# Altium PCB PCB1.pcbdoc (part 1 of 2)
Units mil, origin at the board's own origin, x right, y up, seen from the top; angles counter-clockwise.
Board outline 5331.95 x 5611.34 mil, 4 copper layers (Top Layer, GND, VCC, Bottom Layer); 134 components, 102 nets, 494 pads, 130 vias.
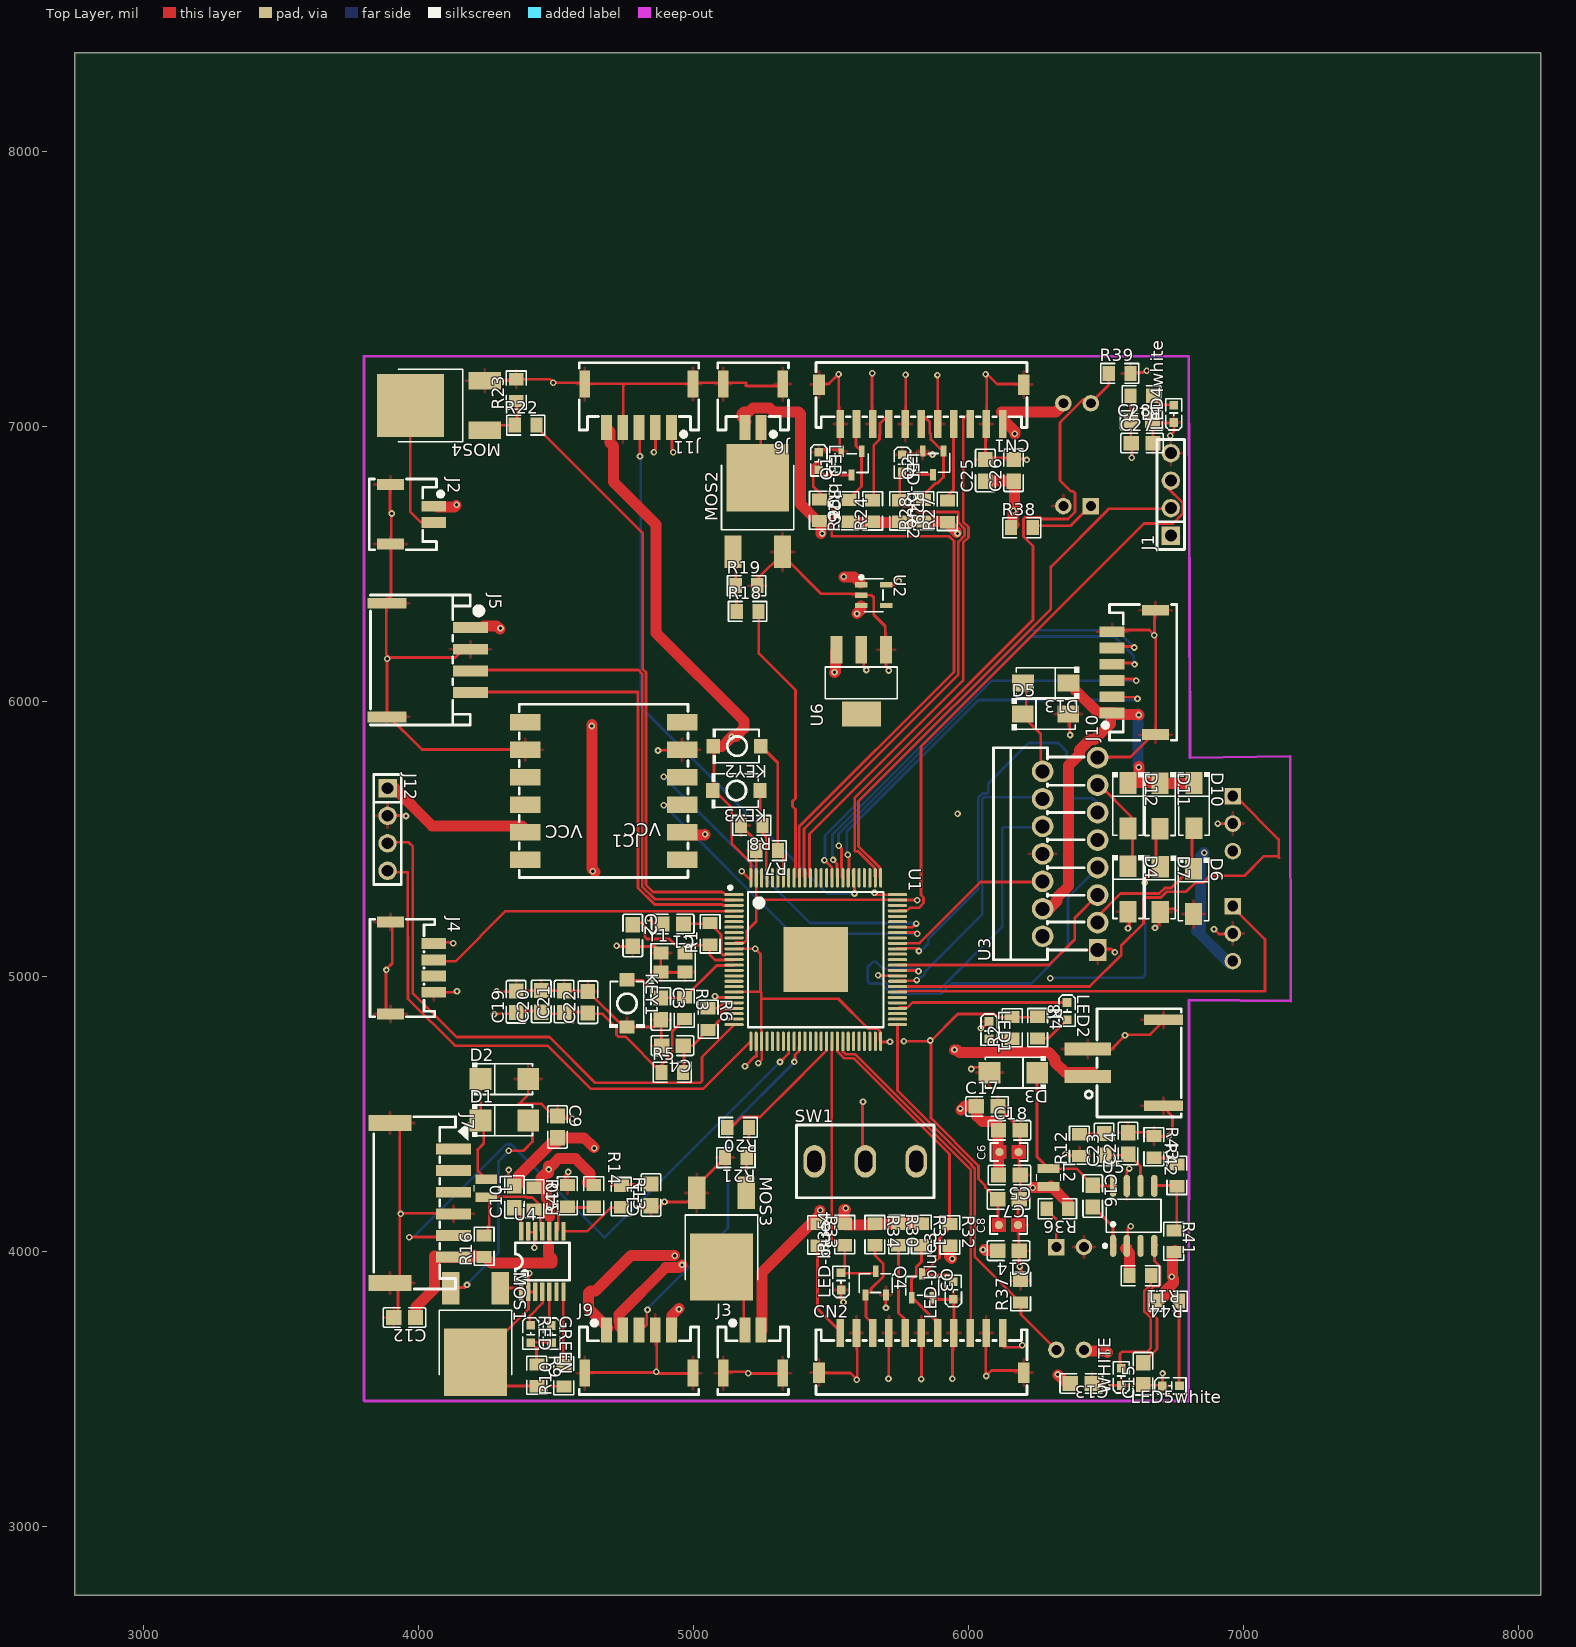
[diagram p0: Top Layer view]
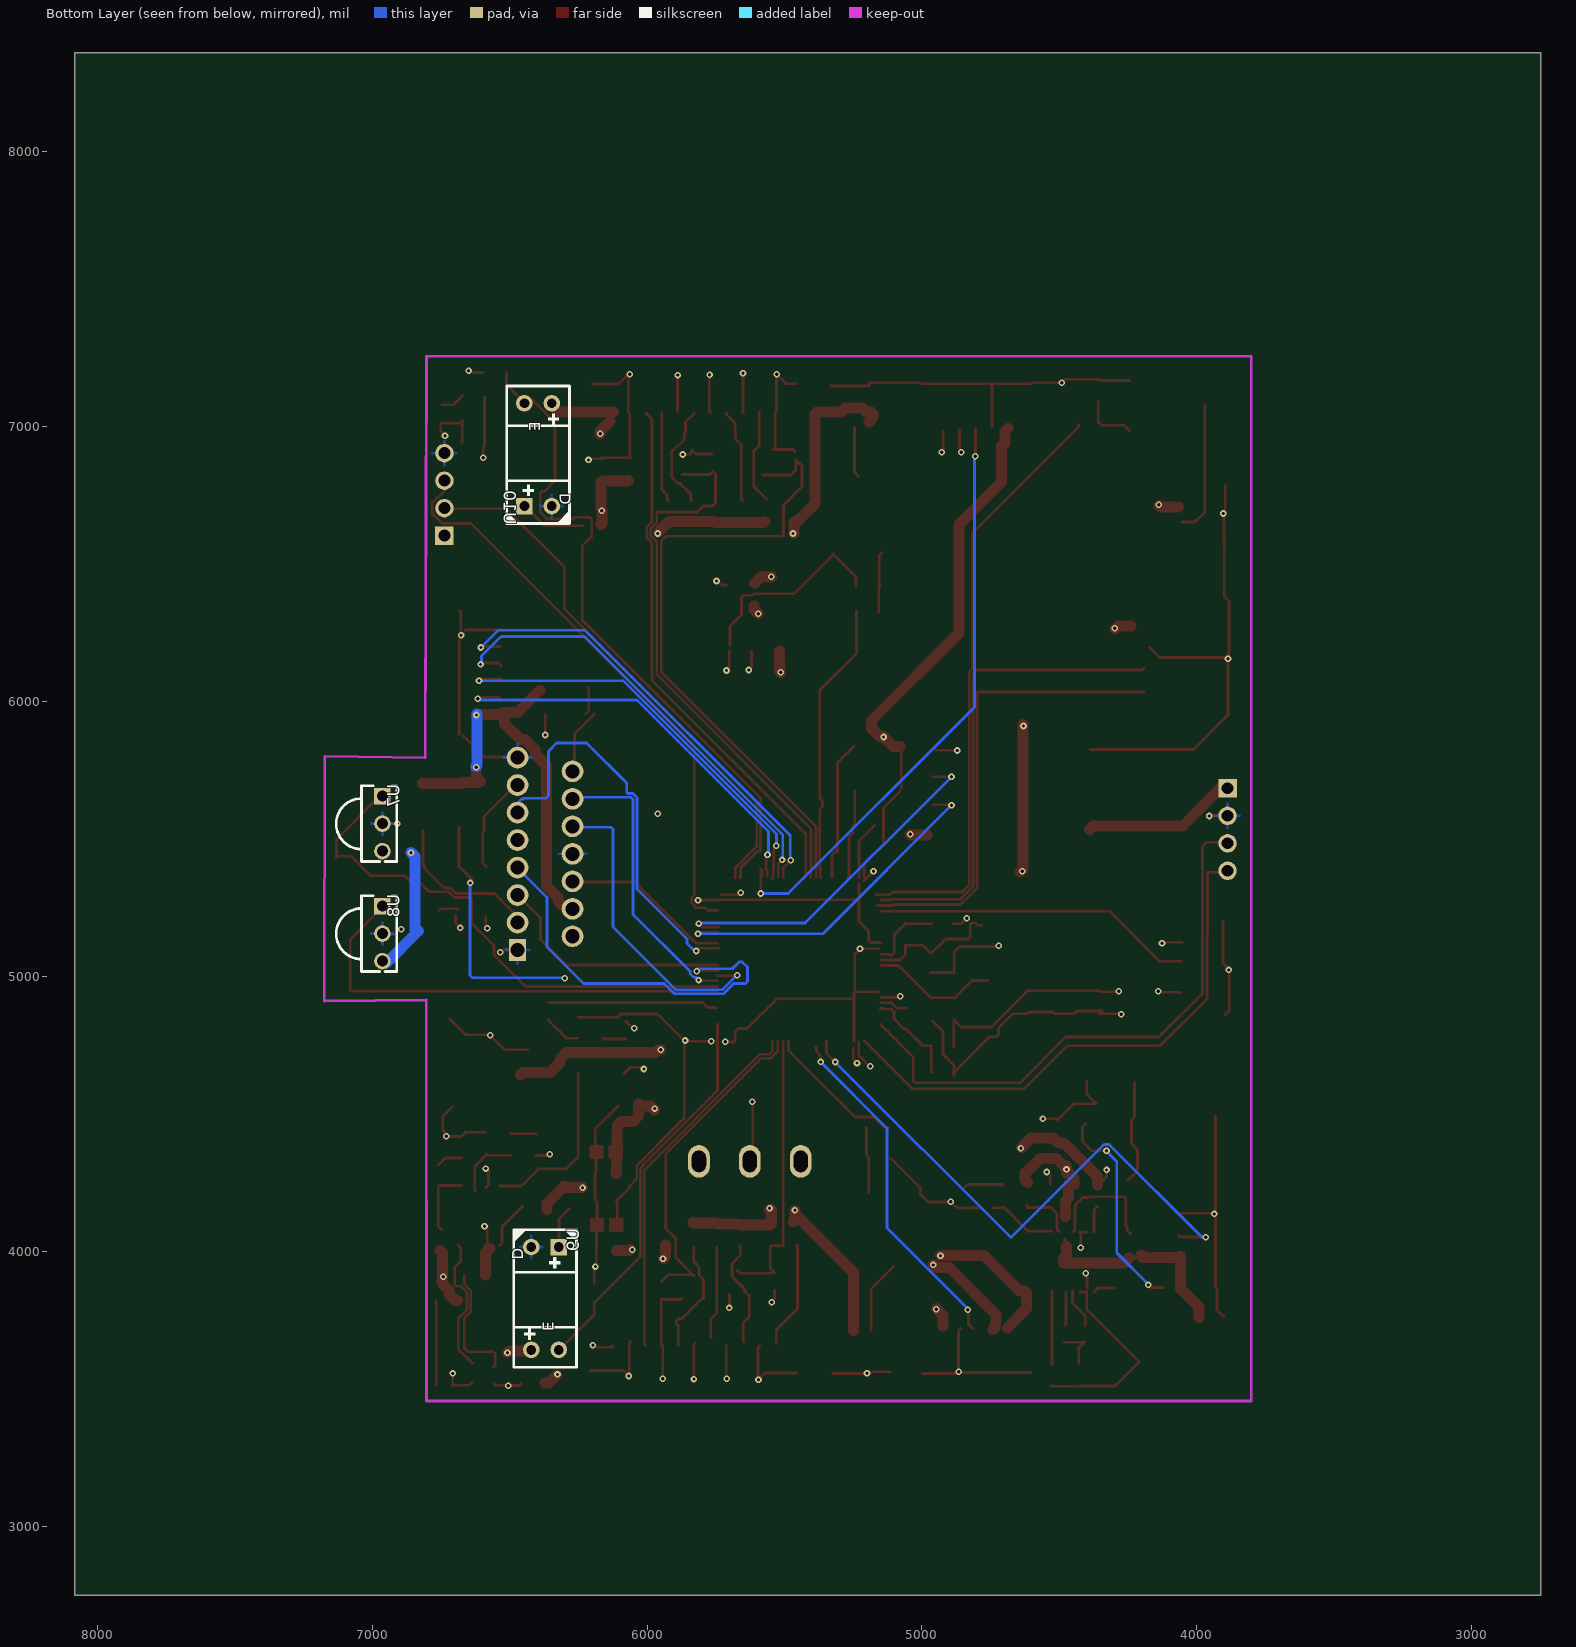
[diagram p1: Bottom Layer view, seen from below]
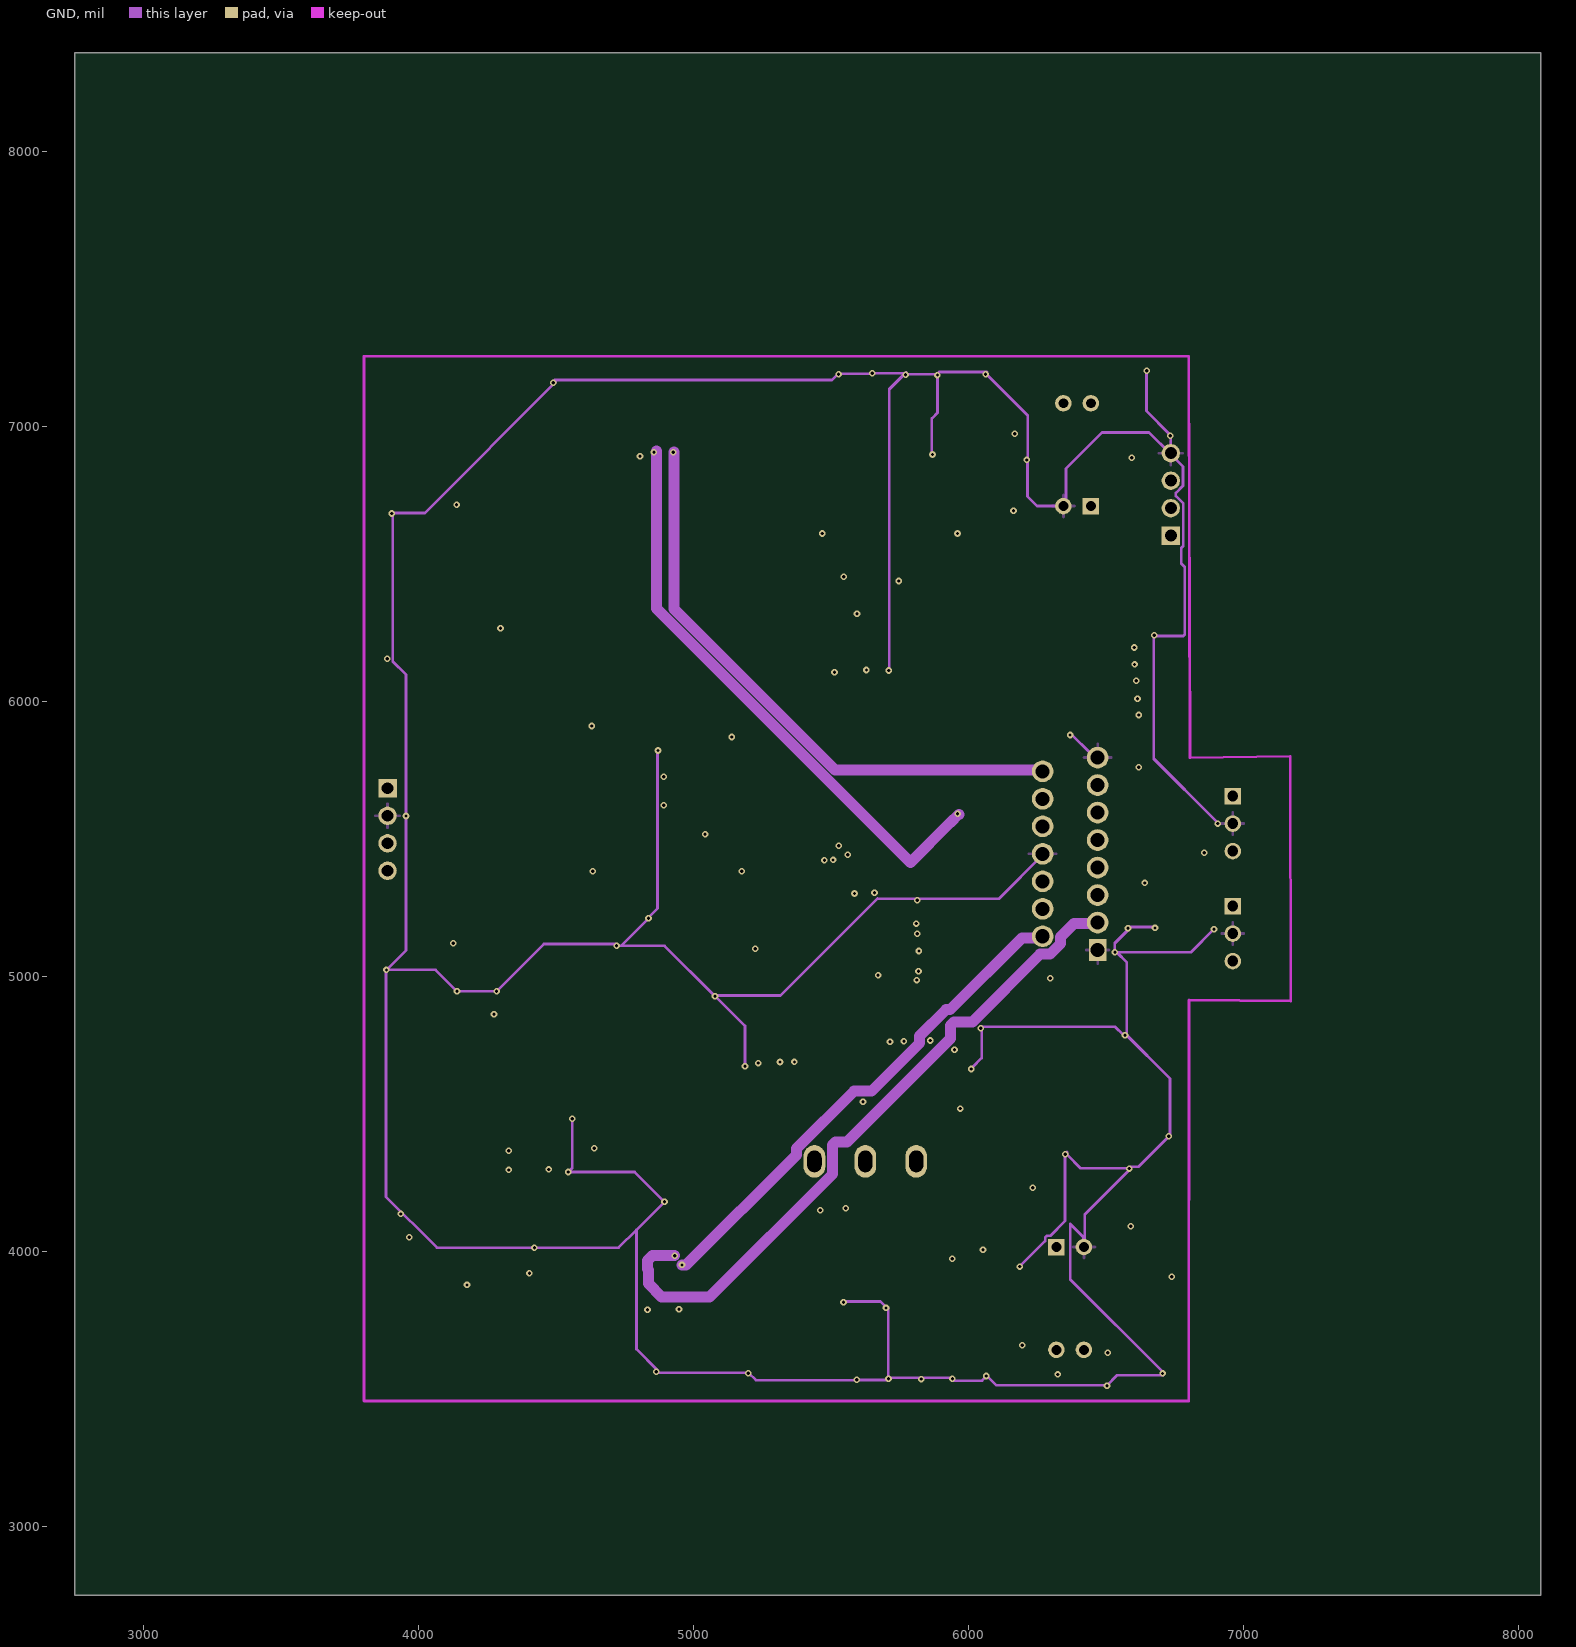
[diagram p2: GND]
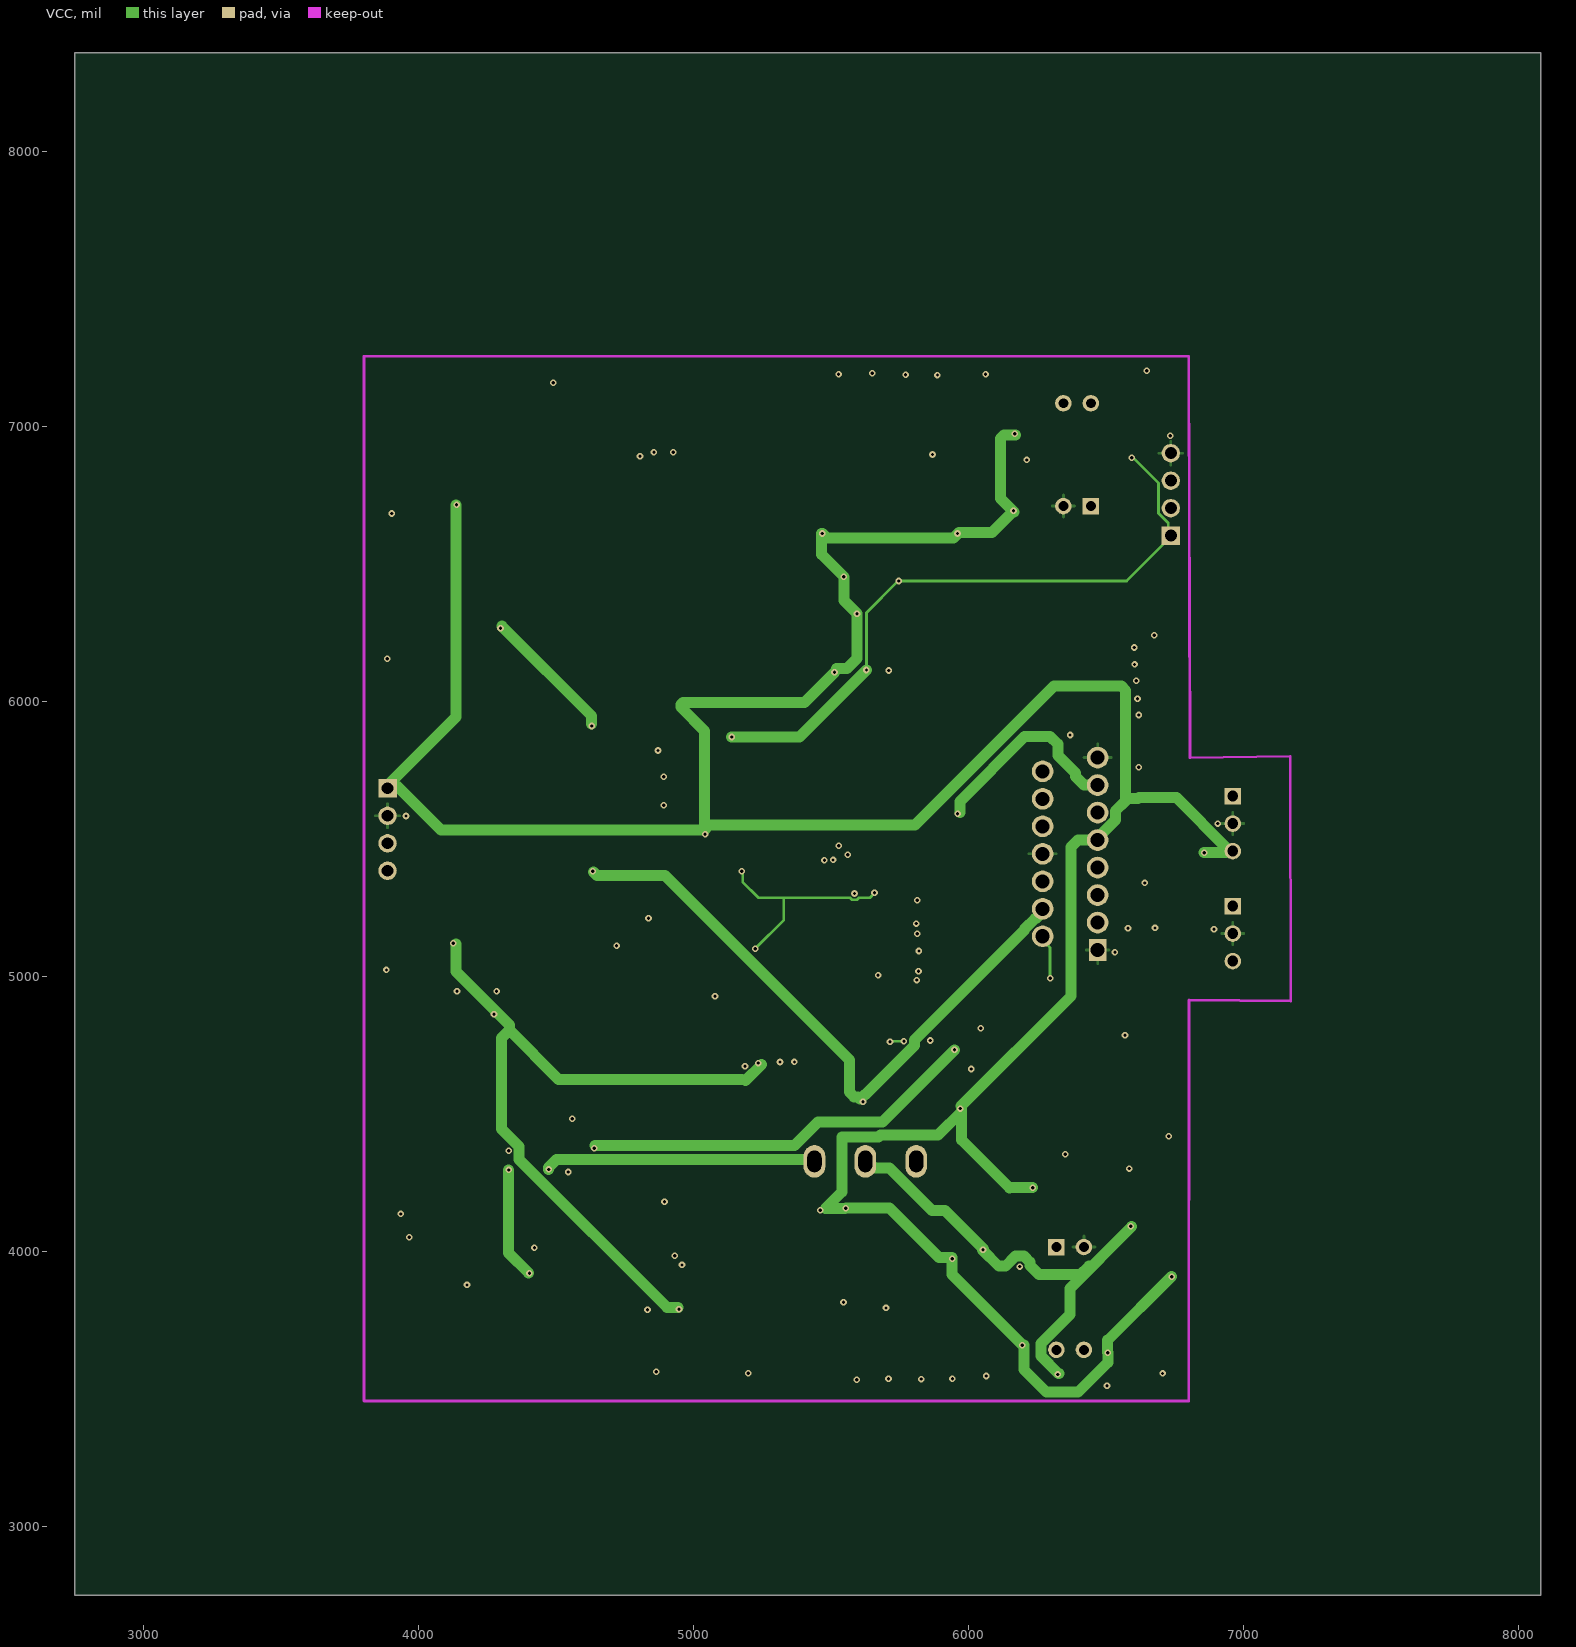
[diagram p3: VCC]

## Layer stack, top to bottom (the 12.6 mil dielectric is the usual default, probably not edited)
Top Layer: signal copper (thickness not stored)
Dielectric: dielectric 12.6, FR-4, Dk 4.8
GND: signal copper (thickness not stored)
Dielectric: dielectric 12.6, FR-4, Dk 4.8
VCC: signal copper (thickness not stored)
Dielectric: dielectric 12.6, FR-4, Dk 4.8
Bottom Layer: signal copper (thickness not stored)

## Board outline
8081.95,2750 2750,2750 2750,8361.34 8081.95,8361.34

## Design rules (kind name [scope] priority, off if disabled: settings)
BoardOutlineClearance copperThickness1oz [All] p0: genericclearance=10 ignorepadtopadclearanceinfootprint=FALSE except(0: Arc-SplitContinuation Track-SplitContinuation SMDPad-SplitContinuation THPad-SplitContinuation Via-SplitContinuation Fill-SplitContinuation Poly-SplitContinuation Region-SplitContinuation Text-SplitContinuation; 6: Track-CutoutEdge SMDPad-CutoutEdge THPad-CutoutEdge Via-CutoutEdge Region-CutoutEdge; 11.8: Track-OutlineEdge SMDPad-OutlineEdge THPad-OutlineEdge Via-OutlineEdge Fill-OutlineEdge Region-OutlineEdge Poly-OutlineEdge Text-OutlineEdge Fill-CutoutEdge)
BoardOutlineClearance copperThickness2oz [All] p0: genericclearance=10 ignorepadtopadclearanceinfootprint=FALSE except(0: Arc-SplitContinuation Track-SplitContinuation SMDPad-SplitContinuation THPad-SplitContinuation Via-SplitContinuation Fill-SplitContinuation Poly-SplitContinuation Region-SplitContinuation Text-SplitContinuation; 6: Track-CutoutEdge SMDPad-CutoutEdge THPad-CutoutEdge Via-CutoutEdge Region-CutoutEdge; 11.8: Track-OutlineEdge SMDPad-OutlineEdge THPad-OutlineEdge Via-OutlineEdge Fill-OutlineEdge Region-OutlineEdge Poly-OutlineEdge Text-OutlineEdge Fill-CutoutEdge)
Clearance copperThickness1oz [(InNet('GND') OR InNet('PH0(OSCIN)') OR InNet('PH1(OSCOUT)') OR InNet('NRST') OR InNet('VDDA') OR InNet('5V') OR InNet('3V3') OR InNet('VIN') OR InNet('$1N159') OR InNet('$1N166') OR InNet('BATTERY+') OR InNet('14V') OR InNet('$1N108') OR InNet('$1N109') OR InNet('$1N121') OR InNet('$1N220') OR InNet('$1N133') OR InNet('IR_CC_L1') OR InNet('IR_BT_FO+') OR InNet('IR_BT_FI-') OR InNet('IR_BT_LO+') OR InNet('IR_BT_LI-') OR InNet('IR_SD_O+') OR InNet('IR_SD_I-') OR InNet('IR_BT_RO+') OR InNet('IR_BT_RI-') OR InNet('IR_CC_R1') OR InNet('$1N9865') OR InNet('$1N9104') OR InNet('$1N104') OR InNet('$1N117') OR InNet('PA9(U1TX)') OR InNet('PA10(U1RX)') OR InNet('PA14(SWCLK)') OR InNet('PA13(SWDIO)') OR InNet('PUMP_O') OR InNet('RB_O') OR InNet('MAGNET') OR InNet('FAN_PWM') OR InNet('FAN_FB') OR InNet('LB_O') OR InNet('RW_O1') OR InNet('RW_O2') OR InNet('LW_O1') OR InNet('LW_O2') OR InNet('BOOT0') OR InNet('PE0') OR InNet('$1N139') OR InNet('$1N60') OR InNet('$1N82') OR InNet('PB15') OR InNet('$1N10537') OR InNet('$1N223') OR InNet('$1N8956') OR InNet('$1N9650') OR InNet('$1N125') OR InNet('$1N103') OR InNet('VREF+') OR InNet('$1N155') OR InNet('$1N156') OR InNet('$1N122') OR InNet('$1N211') OR InNet('FB') OR InNet('$1N221') OR InNet('LB_I') OR InNet('RB_I') OR InNet('PUMP_I') OR InNet('$1N110') OR InNet('PA7PWM') OR InNet('PA6PWM') OR InNet('BAT0') OR InNet('BMQ-R1') OR InNet('BMQ-L1') OR InNet('FRONT1') OR InNet('FRONT2') OR InNet('FRONT3') OR InNet('FRONT4') OR InNet('$1N26') OR InNet('$1N6') OR InNet('IR_BT_L') OR InNet('IR_BT_F') OR InNet('$1N33') OR InNet('$1N34') OR InNet('$1N35') OR InNet('TIM3CH4') OR InNet('TIM3CH3') OR InNet('RWI1') OR InNet('RWI2') OR InNet('LWI1') OR InNet('LWI2') OR InNet('IR_CC_L2') OR InNet('IR_CC_R2') OR InNet('IR_BT_R') OR InNet('IR_SD') OR InNet('$1N11') OR InNet('U2RX') OR InNet('U2TX') OR InNet('$1N18842') OR InNet('IRHIT_L') OR InNet('$1N19000') OR InNet('IRHIT_R') OR InNet('$1N27321'))] p1: gap=7 ignorepadtopadclearanceinfootprint=FALSE except(4: Track-Track; 6: Track-SMDPad SMDPad-SMDPad Track-THPad SMDPad-THPad THPad-THPad Track-Via SMDPad-Via THPad-Via Via-Via SMDPad-Fill THPad-Fill Via-Fill Fill-Fill Track-Region SMDPad-Region THPad-Region Via-Region Region-Region Track-Poly SMDPad-Poly THPad-Poly Via-Poly Fill-Poly Region-Poly Poly-Poly Track-Text SMDPad-Text THPad-Text Via-Text Fill-Text Region-Text Poly-Text Text-Text; 6.9: Track-Hole SMDPad-Hole THPad-Hole Via-Hole Fill-Hole Region-Hole Poly-Hole Text-Hole Sheet-Hole; 11.8: Track-Fill Fill-Region Track-Sheet SMDPad-Sheet THPad-Sheet Via-Sheet Fill-Sheet Region-Sheet Poly-Sheet Text-Sheet)
Clearance copperThickness2oz [All] p1: gap=7 ignorepadtopadclearanceinfootprint=FALSE except(6: Track-SMDPad SMDPad-SMDPad Track-THPad SMDPad-THPad THPad-THPad Track-Via SMDPad-Via THPad-Via Via-Via SMDPad-Fill THPad-Fill Via-Fill Fill-Fill Track-Region SMDPad-Region THPad-Region Via-Region Region-Region Track-Poly SMDPad-Poly THPad-Poly Via-Poly Fill-Poly Region-Poly Poly-Poly Track-Text SMDPad-Text THPad-Text Via-Text Fill-Text Region-Text Poly-Text Text-Text; 6.9: Track-Hole SMDPad-Hole THPad-Hole Via-Hole Fill-Hole Region-Hole Poly-Hole Text-Hole Sheet-Hole; 8: Track-Track; 11.8: Track-Fill Fill-Region Track-Sheet SMDPad-Sheet THPad-Sheet Via-Sheet Fill-Sheet Region-Sheet Poly-Sheet Text-Sheet)
DiffPairsRouting differentialPair [All] p1: maxuncoupledlength=10 minlimit=5.9843 maxlimit=5.9843 mostfreqgap=5.9843 toplayer_minwidth=5 toplayer_prefwidth=10 toplayer_maxwidth=100 bottomlayer_minwidth=5 bottomlayer_prefwidth=10 bottomlayer_maxwidth=100 midlayer1_minwidth=5 midlayer1_prefwidth=10 midlayer1_maxwidth=100 midlayer2_minwidth=5 midlayer2_prefwidth=10 midlayer2_maxwidth=100
PasteMaskExpansion pasteMaskExpansion [All] p1: expansion=0
PlaneConnect innerPlane [All] p1: planeconnectstyle=Relief reliefexpansion=20 reliefentries=4 reliefconductorwidth=10 reliefairgap=10
PolygonConnect copperRegion [All] p1: connectstyle=Relief reliefentries=4 reliefconductorwidth=10 polygonreliefangle="90 Angle" airgapwidth=10
RoutingVias viaSize [All] p1: viastyle="Through Hole" holewidth=12.0078 minholewidth=11.811 maxholewidth=248.0314 width=24.0158 minwidth=19.685 maxwidth=393.7008
SolderMaskExpansion solderMaskExpansion [All] p1: useseparateexpansions=TRUE expansion=2.0079 expansionbottom=2.0079
Width copperThickness1oz [All] p1: maxlimit=100 minlimit=5 preferedwidth=10
Width copperThickness2oz [All] p1: maxlimit=100 minlimit=8 preferedwidth=10

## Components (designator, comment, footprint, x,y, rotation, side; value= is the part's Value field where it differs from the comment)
C1 "" C0805 4925.37,5191.91 r180 top
C2 "" C0805 4780.08,5150.23 r270 top
C3 "" C0805 4881.96,4883.12 r270 top
C4 "" C0805 4924.48,4749.45 r180 top
C5 "" C0805 6149.91,4278.78 r180 top
C6 "" c8050 6108.79,4327.34 r0 top
C7 "" C0805 6146.8,4190.09 r180 top
C8 "" c8050 6106.84,4062.02 r0 top
C9 "" C0805 4506.34,4454.12 r270 top
C10 "" C0805 4349.38,4199.56 r90 top
C11 "" C0805 4846.36,4206.63 r90 top
C12 "" C0805 3950.11,3760.71 r180 top
C13 "" C0805 6411.09,3520.56 r180 top
C14 "" C0805 6146.75,4003.8 r180 top
C15 "" C0805 6636.18,3556.28 r90 top
C16 "" C0805 6453.08,4202.32 r270 top
C17 "" C0805 6069.11,4528.59 r0 top
C18 "" C0805 6149.94,4441.68 r0 top
C19 "" C0805 4355.83,4908.99 r90 top
C20 "" C0805 4447.13,4910.47 r90 top
C21 "" C0805 4530.46,4909.68 r90 top
C22 "" C0805 4616.89,4907.36 r90 top
C23 "" C0805 6494.46,4390.35 r90 top
C24 "" C0805 6581.62,4393.71 r90 top
C25 "" C0805 6062.38,6841.73 r90 top
C26 "" C0805 6165.35,6842.18 r90 top
C27 "" C0805 6632.55,6941.05 r0 top
C28 "" C0805 6631.55,7023.48 r0 top
CN1 "" CONN-SMD_11P-P1.50_HCTL_HC-ZH-11PWT 5830.05,7082.06 r180 top locked
CN2 "" CONN-SMD_11P-P1.50_HCTL_HC-ZH-11PWT 5830.04,3632.06 r0 top locked
D1 "" SMA_L4.3-W2.6-LS5.1-RD 4313.03,4477.46 r0 top
D2 "" SMA_L4.3-W2.6-LS5.1-RD 4313.09,4627.94 r0 top
D3 "" SMA_L4.3-W2.6-LS5.1-RD 6164.43,4651.41 r180 top
D4 "" SMA_L4.3-W2.5-LS5.0-RD 6581.73,5319.22 r270 top
D5 "" SMA_L4.3-W2.5-LS5.0-RD 6281.7,5955.42 r0 top
D6 "" SMA_L4.3-W2.5-LS5.0-RD 6819.97,5310.82 r270 top
D7 "" SMA_L4.3-W2.5-LS5.0-RD 6698.65,5318 r270 top
D10 "" SMA_L4.3-W2.5-LS5.0-RD 6821.27,5622.32 r270 top
D11 "" SMA_L4.3-W2.5-LS5.0-RD 6698.24,5621.08 r270 top
D12 "" SMA_L4.3-W2.5-LS5.0-RD 6581.45,5621.86 r270 top
D13 "" SMA_L4.3-W2.5-LS5.0-RD 6282.22,6068.87 r180 top
GREEN "" LED0603-RD_1 4484.27,3700.16 r270 top
IC1 "ATK-IMU901" COMM-SMD_12P-L16.0-W15.5-P2.54_ATK-IMU901 4674.14,5676 r180 top
J1 "" HDR-TH_4P-P2.54-V-M 6737.08,6754.45 r90 top
J2 "" CONN-SMD_2P-P1.50_ZX-ZH1.5-2PWT 3977.55,6682.06 r270 top locked
J3 "" CONN-SMD_2P-P1.50_ZX-ZH1.5-2PWT 5217.55,3637.06 r0 top locked
J4 "" CONN-SMD_4P-P1.50_ZX-ZH1.5-4PWT 3977.55,5032.06 r270 top locked
J5 "" CONN-SMD_4P-P2.00_USAKRO_UK-2.0-4AWT 4037.55,6152.06 r270 top locked
J6 "" CONN-SMD_2P-P1.50_ZX-ZH1.5-2PWT 5217.55,7077.06 r180 top locked
J7 "" CONN-SMD_6P-P2.00_HCTL_HC-PH-6AWT 4012.55,4177.06 r270 top locked
J8 "" CONN-SMD_2P-P2.54_USAKRO_UK-2.54-2AWT 6572.55,4687.06 r90 top locked
J9 "" CONN-SMD_5P-P1.50_ZX-ZH1.5-5PWT 4802.55,3637.06 r0 top locked
J10 "" CONN-SMD_6P-P1.50_ZX-ZH1.5-6PWT 6602.55,6107.06 r90 top locked
J11 "" CONN-SMD_5P-P1.50_ZX-ZH1.5-5PWT 4802.55,7077.06 r180 top locked
J12 "" HDR-TH_4P-P2.54-V-M 3888.29,5535.56 r270 top
KEY1 "" SW-SMD_L3.9-W3.0-P4.45 4759.12,4903.24 r270 top
KEY2 "" SW-SMD_L3.9-W3.0-P4.45 5159.34,5838.9 r180 top
KEY3 "" SW-SMD_L3.9-W3.0-P4.45 5156.87,5677.31 r180 top
L1 "" IND-SMD_L2.5-W2.0-VLS252012CX-150M 4246.63,4230.87 r270 top
L2 "" IND-SMD_L2.5-W2.0-VLS252012CX-150M 6292.17,4269.58 r270 top
LED1 "" LED0603-RD_1 6075.86,4805.99 r270 top
LED2 "" LED0603-RD_1 6359.72,4874.9 r270 top
LED4white "" LED0603-RD_1 6748.06,7047.36 r90 top
LED5white "" LED0603-RD_1 6737.44,3511.85 r0 top
LED-blue "" LED0603-RD_1 5456.76,6876.09 r270 top
LED-blue2 "" LED0603-RD_1 5760.45,6867.66 r270 top
LED-blue3 "" LED0603-RD_1 5946.23,3859.01 r90 top
LED-blue4 "" LED0603-RD_1 5537.74,3892.07 r90 top
MOS1 "" TO-252-2_L6.6-W6.1-P4.57-LS10.1-TL-CW 4207.84,3732.51 r270 top
MOS2 "" TO-252-2_L6.6-W6.1-P4.57-LS10.1-TL-CW 5234.47,6680.18 r90 top
MOS3 "" TO-252-2_L6.6-W6.1-P4.57-LS10.1-TL-CW 5102.46,4079.15 r270 top
MOS4 "" TO-252-2_L6.6-W6.1-P4.57-LS10.1-TL-CW 4107.05,7077.62 r180 top
Q1 "" SOT-23-3_L3.0-W1.7-P0.95-LS2.9-BR 5575.95,6868 r90 top
Q2 "" SOT-23-3_L3.0-W1.7-P0.95-LS2.9-BR 5872.47,6869.41 r90 top
Q3 "" SOT-23-3_L3.0-W1.7-P0.95-LS2.9-BR 5832.49,3876.03 r270 top
Q4 "" SOT-23-3_L3.0-W1.7-P0.95-LS2.9-BR 5663.57,3885.66 r270 top
R1 "" R0805 5061.35,5155.85 r90 top
R2 "" R0805 6160.18,4814.36 r90 top
R3 "" R0805 4967.64,4885.88 r270 top
R4 "" R0805 6252.59,4815.17 r270 top
R5 "" R0805 4923.57,4652.42 r0 top
R6 "" R0805 5054.09,4845.79 r270 top
R7 "" R0805 5268.92,5458.93 r180 top
R8 "" R0805 5212.93,5550.32 r180 top
R9 "" R0805 4431.11,3550.31 r270 top
R10 "" R0805 4529.36,3548.96 r90 top
R11 "" R0805 6626.45,3912.74 r180 top
R12 "" R0805 6404.64,4387.37 r90 top
R13 "" R0805 4738.38,4200.69 r270 top
R14 "" R0805 4638.04,4203.24 r270 top
R15 "" R0805 4420.55,4192.9 r270 top
R16 "" R0805 4239.47,4019.98 r90 top
R17 "" R0805 6630.06,7113.4 r180 top
R18 "" R0805 5197.68,6328.78 r0 top
R19 "" R0805 5193.94,6422.5 r0 top
R20 "" R0805 5163.12,4451.86 r180 top
R21 "" R0805 5155.08,4342.28 r180 top
R22 "" R0805 4390.64,7006.82 r0 top
R23 "" R0805 4356.38,7133.87 r90 top
R24 "510R" R0805 5652.24,6694.32 r90 top
R25 "10k" R0805 5566.01,6694.8 r90 top
R26 "1k" R0805 5459.08,6696.82 r270 top
R27 "510R" R0805 5924.21,6692.76 r90 top
R28 "10k" R0805 5838.13,6695.13 r90 top
R29 "1k" R0805 5750.45,6694.31 r270 top
R30 "510R" R0805 5746.97,4062.41 r270 top
R31 "10k" R0805 5830.22,4062.74 r270 top
R32 "1k" R0805 5933.71,4060.95 r270 top
R33 "510R" R0805 5453.22,4061.05 r270 top
R34 "10k" R0805 5660.76,4062.42 r270 top
R35 "1k" R0805 5550.96,4062.37 r90 top
R36 "200R" R0805 6324.86,4156.09 r180 top
R37 "1k" R0805 6190.72,3854.94 r90 top
R38 "200R" R0805 6195.15,6633.45 r0 top
R39 "1k" R0805 6551,7194.5 r0 top
R40 "" R0805 4542.3,4203.22 r90 top
R41 "" R0805 6748.15,4037.84 r270 top
R42 "" R0805 6759.15,4277.61 r270 top
R43 "" R0805 6675.61,4381.38 r270 top
R44 "1k" R0805 6727.44,3820.32 r180 top
RED "" LED0603-RD_1 4408.7,3700.51 r270 top
SW1 "" SW-TH_SS-12D10L5 5626.04,4328.52 r0 top
U1 "" LQFP-100_L14.0-W14.0-P0.50-LS16.0-BL-EP6.0 5445.71,5062.41 r270 top
U2 "" SOT-23-5_L3.0-W1.7-P0.95-LS2.8-BL 5656.47,6388.03 r270 top
U3 "" MULTIWATT-15_L19.6-W5.0-P1.27-L 6370.99,5447.28 r90 top
U4 "" TSSOP-14_L5.0-W4.4-P0.65-LS6.4-BL 4451.2,3964.32 r0 top
U5 "" SOIC-8_L4.9-W3.9-P1.27-LS6.0-BL 6602.1,4130.26 r0 top
U6 "" SOT-223-3_L6.5-W3.4-P2.30-LS7.0-BR 5611.27,6072.61 r90 top
U7 "" OPTO-TH_3P-L7.0-W5.6-P2.54-L 6962.55,5557.06 r270 bottom locked
U8 "" OPTO-TH_3P-L7.0-W5.6-P2.54-L 6962.55,5157.06 r270 bottom locked
U9 "" OPTO-TH_L12.7-W5.8_ST150 6371.01,3830.06 r270 bottom
U10 "" OPTO-TH_L12.7-W5.8_ST150 6396.37,6899.05 r90 bottom locked
WHITE "" LED0603-RD_1 6556.93,3544.64 r90 top
Y1 "" OSC-SMD_4P-L3.2-W2.5-BL 4926.28,5051.7 r0 top

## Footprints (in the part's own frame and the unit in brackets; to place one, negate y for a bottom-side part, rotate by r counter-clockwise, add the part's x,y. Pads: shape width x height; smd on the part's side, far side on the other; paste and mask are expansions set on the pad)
C0805 [mm]
  rect 1.41x1.35 smd: 1(-1,0) 2(1,0)
  silkscreen extent -1.96,-0.9 1.96,0.9
c8050 [mil]
  oval 30x30.13 smd: 1(5,34.97)
  oval 30.35x30 smd: 2(74.71,35)
  Top Layer region: -20,9.95 29.95,9.95 30,9.9 30,60.12 29.88,60 -20,60
  Top Layer region: 49.41,59.95 50,59.36 50,10 100,10 100,60 49.46,60
  silkscreen extent -28,2 108,68
COMM-SMD_12P-L16.0-W15.5-P2.54_ATK-IMU901 [mm]
  rect 2.8x1.524 smd: 1(-7.25,6.35) 2(-7.25,3.81) 3(-7.25,1.27) 4(-7.25,-1.27) 5(-7.25,-3.81) 6(-7.25,-6.35) 7(7.25,-6.35) 8(7.25,-3.81) 9(7.25,-1.27) 10(7.25,1.27) 11(7.25,3.81) 12(7.25,6.35)
  silkscreen extent -7.8,-8 7.8,8
CONN-SMD_2P-P1.50_ZX-ZH1.5-2PWT [mm]
  rect 1x2.3 smd: 1(-0.75,2) 2(0.75,2)
  rect 1x2.5 smd: 3(2.75,-2) 4(-2.75,-2)
  silkscreen extent -3.27,-3.97 3.27,3.04
CONN-SMD_2P-P2.54_USAKRO_UK-2.54-2AWT [mm]
  rect 1.2x4.3 smd: 1(-1.27,3.5) 2(1.27,3.5)
  rect 1x3.6 smd: 3(3.97,-3.5) 4(-3.97,-3.5)
  silkscreen extent -5.01,-5.15 5,3.73
CONN-SMD_4P-P1.50_ZX-ZH1.5-4PWT [mm]
  rect 1x2.3 smd: 1(-2.25,2) 2(-0.75,2) 3(0.75,2) 4(2.25,2)
  rect 1x2.5 smd: 5(4.25,-2) 6(-4.25,-2)
  silkscreen extent -4.5,-3.9 4.5,2.1
CONN-SMD_4P-P2.00_USAKRO_UK-2.0-4AWT [mm]
  rect 1x3.25 smd: 1(-3,3.862) 2(-1,3.862) 3(1,3.862) 4(3,3.862)
  rect 1x3.6 smd: 5(-5.25,-3.862) 6(5.25,-3.862)
  silkscreen extent -6,-5.36 6,4.93
CONN-SMD_5P-P1.50_ZX-ZH1.5-5PWT [mm]
  rect 1x2.3 smd: 1(-3,2) 2(-1.5,2) 3(0,2) 4(1.5,2) 5(3,2)
  rect 1x2.5 smd: 6(5,-2) 7(-5,-2)
  silkscreen extent -5.52,-3.97 5.52,3.04
CONN-SMD_6P-P1.50_ZX-ZH1.5-6PWT [mm]
  rect 1x2.3 smd: 1(-3.75,2) 2(-2.25,2) 3(-0.75,2) 4(0.75,2) 5(2.25,2) 6(3.75,2)
  rect 1x2.5 smd: 7(5.75,-2) 8(-5.75,-2)
  silkscreen extent -6.27,-3.97 6.27,3.04
CONN-SMD_6P-P2.00_HCTL_HC-PH-6AWT [mm]
  rect 1x3.25 smd: 1(-5,2.938) 2(-3,2.938) 3(-1,2.938) 4(1,2.938) 5(3,2.938) 6(5,2.938)
  rect 1.5x4 smd: 7(7.4,-2.938) 8(-7.4,-2.938)
  silkscreen extent -7.96,-4.44 7.94,4.29
CONN-SMD_11P-P1.50_HCTL_HC-ZH-11PWT [mm]
  rect 0.7x2.6 smd: 1(-7.5,1.825) 2(-6,1.825) 3(-4.5,1.825) 4(-3,1.825) 5(-1.5,1.825) 6(0,1.825) 7(1.5,1.825) 8(3,1.825) 9(4.5,1.825) 10(6,1.825) 11(7.5,1.825)
  rect 1.1x1.9 smd: 12(9.45,-1.825) 13(-9.45,-1.825)
  silkscreen extent -9.75,-3.86 9.75,2.14
HDR-TH_4P-P2.54-V-M [mm]
  rect 1.7x1.7 hole 1.1: 1(-3.81,0)
  round 1.7 hole 1.1: 2(-1.27,0) 3(1.27,0) 4(3.81,0)
  silkscreen extent -5.08,-1.27 5.08,1.27
IND-SMD_L2.5-W2.0-VLS252012CX-150M [mm]
  rect 0.85x2 smd: 1(-0.83,0) 2(0.83,0)
  silkscreen extent -0.29,-1.1 0.29,1.1
LED0603-RD_1 [mm]
  rect 0.8x0.8 smd: 1(-0.8,-0.003) 2(0.8,0.003)
  silkscreen extent -1.49,-0.75 1.39,0.76
LQFP-100_L14.0-W14.0-P0.50-LS16.0-BL-EP6.0 [mm]
  oval 0.28x1.8 smd: 1(-6,-7.55) 2(-5.5,-7.55) 3(-5,-7.55) 4(-4.5,-7.55) 5(-4,-7.55) 6(-3.5,-7.55) 7(-3,-7.55) 8(-2.5,-7.55) 9(-2,-7.55) 10(-1.5,-7.55) 11(-1,-7.55) 12(-0.5,-7.55) 13(0,-7.55) 14(0.5,-7.55) 15(1,-7.55) 16(1.5,-7.55) 17(2,-7.55) 18(2.5,-7.55) 19(3,-7.55) 20(3.5,-7.55) 21(4,-7.55) 22(4.5,-7.55) 23(5,-7.55) 24(5.5,-7.55) 25(6,-7.55) 51(6,7.55) 52(5.5,7.55) 53(5,7.55) 54(4.5,7.55) 55(4,7.55) 56(3.5,7.55) 57(3,7.55) 58(2.5,7.55) 59(2,7.55) 60(1.5,7.55) 61(1,7.55) 62(0.5,7.55) 63(0,7.55) 64(-0.5,7.55) 65(-1,7.55) 66(-1.5,7.55) 67(-2,7.55) 68(-2.5,7.55) 69(-3,7.55) 70(-3.5,7.55) 71(-4,7.55) 72(-4.5,7.55) 73(-5,7.55) 74(-5.5,7.55) 75(-6,7.55)
  oval 1.8x0.28 smd: 26(7.55,-6) 27(7.55,-5.5) 28(7.55,-5) 29(7.55,-4.5) 30(7.55,-4) 31(7.55,-3.5) 32(7.55,-3) 33(7.55,-2.5) 34(7.55,-2) 35(7.55,-1.5) 36(7.55,-1) 37(7.55,-0.5) 38(7.55,0) 39(7.55,0.5) 40(7.55,1) 41(7.55,1.5) 42(7.55,2) 43(7.55,2.5) 44(7.55,3) 45(7.55,3.5) 46(7.55,4) 47(7.55,4.5) 48(7.55,5) 49(7.55,5.5) 50(7.55,6) 76(-7.55,6) 77(-7.55,5.5) 78(-7.55,5) 79(-7.55,4.5) 80(-7.55,4) 81(-7.55,3.5) 82(-7.55,3) 83(-7.55,2.5) 84(-7.55,2) 85(-7.55,1.5) 86(-7.55,1) 87(-7.55,0.5) 88(-7.55,0) 89(-7.55,-0.5) 90(-7.55,-1) 91(-7.55,-1.5) 92(-7.55,-2) 93(-7.55,-2.5) 94(-7.55,-3) 95(-7.55,-3.5) 96(-7.55,-4) 97(-7.55,-4.5) 98(-7.55,-5) 99(-7.55,-5.5) 100(-7.55,-6)
  rect 6x6 smd: 101(0,0)
  silkscreen extent -6.8,-8.05 6.25,6.25
MULTIWATT-15_L19.6-W5.0-P1.27-L [mm]
  rect 2x1.6 hole 1.3: 1(-8.89,-2.54)
  round 2 hole 1.3: 2(-7.62,2.54) 3(-6.35,-2.54) 4(-5.08,2.54) 5(-3.81,-2.54) 6(-2.54,2.54) 7(-1.27,-2.54) 8(0,2.54) 9(1.27,-2.54) 10(2.54,2.54) 11(3.81,-2.54) 12(5.08,2.54) 13(6.35,-2.54) 14(7.62,2.54) 15(8.89,-2.54)
  silkscreen extent -9.8,-1.52 9.8,7.09
OPTO-TH_3P-L7.0-W5.6-P2.54-L [mil]
  rect 60x60 hole 39.37: 1(-100,0)
  round 60 hole 39.37: 2(0,0) 3(100,0)
  silkscreen extent -138,-168 138,52
OPTO-TH_L12.7-W5.8_ST150 [mil]
  rect 60x60 hole 36: 1(-187.01,50)
  round 60 hole 36: 2(-187.01,-50) 3(187.01,50) 4(187.01,-50)
  silkscreen extent -250,-115 250,115
OSC-SMD_4P-L3.2-W2.5-BL [mm]
  rect 1.4x1.2 smd: 1(-1.1,-0.875) 2(1.1,-0.875) 3(1.1,0.875) 4(-1.1,0.875)
  silkscreen extent -2.29,-1.9 2.07,1.72
R0805 [mm]
  rect 1.133x1.377 smd: 1(-1,0) 2(1,0)
  silkscreen extent -1.76,-0.92 1.76,0.92
SMA_L4.3-W2.5-LS5.0-RD [mm]
  rect 2x1.593 smd: 1(-2.1,0) 2(2.1,0)
  silkscreen extent -3.11,-1.48 2.73,1.48
SMA_L4.3-W2.6-LS5.1-RD [mm]
  rect 2x2 smd: 1(-2.2,0) 2(2.2,0)
  silkscreen extent -2.98,-1.5 2.6,1.5
SOIC-8_L4.9-W3.9-P1.27-LS6.0-BL [mm]
  oval 0.588x2.045 smd: 1(-1.905,-2.772) 2(-0.635,-2.772) 3(0.635,-2.772) 4(1.905,-2.772) 5(1.905,2.772) 6(0.635,2.772) 7(-0.635,2.772) 8(-1.905,2.772)
  silkscreen extent -2.8,-2.92 2.53,1.52
SOT-23-3_L3.0-W1.7-P0.95-LS2.9-BR [mil]
  rect 40.85x20.95 smd: 1(43.36,-37.4) 2(43.36,37.4) 3(-43.36,0)
  silkscreen extent -34,-60 34,60
SOT-23-5_L3.0-W1.7-P0.95-LS2.8-BL [mm]
  rect 0.49x1.157 smd: 1(-0.95,-1.154) 2(0,-1.154) 3(0.95,-1.154)
  rect 0.49x1.175 smd: 4(0.95,1.154) 5(-0.95,1.154)
  silkscreen extent -1.8,-1.29 1.53,0.85
SOT-223-3_L6.5-W3.4-P2.30-LS7.0-BR [mm]
  rect 2.5x1.1 smd: 1(2.97,-2.3) 2(2.97,0) 3(2.97,2.3)
  rect 2.34x3.6 smd: 4(-2.97,0)
  silkscreen extent -1.57,-3.33 1.37,3.33
SW-SMD_L3.9-W3.0-P4.45 [mm]
  rect 1.23x1.36 smd: 1(-2.185,0) 2(2.185,0)
  silkscreen extent -2.03,-1.62 2.25,1.62
SW-TH_SS-12D10L5 [mm]
  oval 2x3 hole 1.3 slot 2 at 90 deg: 1(-4.7,0) 2(0,0) 3(4.7,0)
  silkscreen extent -6.35,-3.35 6.35,3.35
TO-252-2_L6.6-W6.1-P4.57-LS10.1-TL-CW [mm]
  rect 3x1.6 smd: 1(-3.424,2.285) 3(-3.424,-2.285)
  rect 6.2x5.8 smd: 2(3.424,0)
  silkscreen extent -1.38,-3.35 4.58,3.35
TSSOP-14_L5.0-W4.4-P0.65-LS6.4-BL [mm]
  rect 0.4x1.7 smd: 1(-1.95,-2.8) 2(-1.3,-2.8) 3(-0.65,-2.8) 4(0,-2.8) 5(0.65,-2.8) 6(1.3,-2.8) 7(1.95,-2.8) 8(1.95,2.8) 9(1.3,2.8) 10(0.65,2.8) 11(0,2.8) 12(-0.65,2.8) 13(-1.3,2.8) 14(-1.95,2.8)
  silkscreen extent -2.51,-1.74 2.5,1.74

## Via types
v1: diameter 24.02, hole 12.01, Top Layer to Bottom Layer, 130 vias

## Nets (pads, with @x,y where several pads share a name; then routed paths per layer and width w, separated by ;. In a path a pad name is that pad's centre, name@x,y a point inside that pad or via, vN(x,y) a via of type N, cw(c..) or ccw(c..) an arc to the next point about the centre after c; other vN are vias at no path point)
3V3: C7.2 C8.1 C19.1 C20.1 C21.1 C22.1 C27.1 C28.1 J1.1 J4.1 J9.5 J11.5 KEY2.2 KEY3.2 R2.2 R3.2 R4.1 R5.1 R17.2 U1.11 U1.19 U1.28 U1.50 U1.75 U1.100 U2.5 U6.2 | length 11802.8
  Top Layer w10: J4.1@4053.53,5125.53 4113.14,5125.53 v1@4121.92,5116.75 ; v1@4276.67,4860.74 4281.27,4865.34 C19.1@4354.47,4865.34 ; C19.1@4344.68,4875.17 4436.91,4875.17 C20.1@4446.95,4865.13 ; C20.1@4447.58,4865.13 4515.98,4865.13 C21.1@4522.88,4872.03 ; C21.1@4525.39,4871.41 C22.1@4610.72,4871.41 ; C22.1@4616.37,4865.13 4670.33,4865.13 4721.36,4814.1 4721.36,4788.46 4727.8,4782.02 4753.44,4782.02 R5.1@4883.33,4652.14 ; R5.1@4883.33,4640.71 R5.1@4883.33,4652.14 ; R5.1@4886.81,4648.65 R5.1@4883.33,4652.14 ; R3.2@4963.64,4840.66 4923.85,4800.87 4923.85,4718.32 4883.33,4677.8 R5.1@4883.33,4652.14 ; KEY3.2@5074.46,5688.19 5075.41,5689.13 KEY2.2@5075.41,5836.9 ; KEY3.2@5078.64,5675.31 5140.28,5613.66 5140.28,5483.27 5210.4,5413.15 U1.100@5210.4,5361.89 ; U1.11@5157.49,5101.8 5225.12,5101.8 v1(5225.5,5102.18) 5244.46,5083.22 5244.46,4945.29 5161.46,4945.29 U1.19@5159.82,4943.65 ; v1@5172.97,5384.79 5175.48,5384.79 U1.100@5211.87,5348.4 ; v1(5236.12,4686.09) 5249.5,4699.47 U1.28@5249.5,4740.76 ; U1.28@5247.25,4764.62 5247.25,4943.61 ; 5248.12,4919.95 5527.48,4919.95 5635.84,4811.59 5669.09,4811.59 5678.75,4801.92 5678.75,4768.68 U1.50@5683.04,4764.39 ; U6.2@5620.39,6182.87 5620.39,6125.32 v1(5629.88,6115.82) ; v1(5659.21,5306.03) 5666.74,5298.5 U1.75@5730.74,5298.5 ; U1.50@5683.04,4762.9 5708.29,4762.9 v1@5710.53,4765.14 ; U2.5@5711.37,6425.08 5729.57,6425.08 v1@5746.51,6442.02 ; v1(5766.36,4765.73) 5855.28,4765.73 v1@5860.34,4770.79 ; v1@5864.47,4769.53 5864.47,4485.59 6037.74,4312.31 6037.74,4264 6062.62,4239.12 6062.62,4233.26 C7.2@6110.72,4185.16 ; v1@5865.96,4768.04 5962.12,4864.2 6096.03,4864.2 6106.62,4853.61 ; 6106.62,4853.1 R2.2@6157.47,4853.1 ; C8.1@6108.42,4097 C7.2@6108.42,4185.16 ; C7.2@6108.42,4187.99 C7.2@6110.3,4189.87 ; R2.2@6157.05,4853.52 R2.2@6157.47,4853.1 ; R4.1@6249.92,4853.1 R2.2@6157.47,4853.1 ; C27.1@6591.26,6938.68 R17.2@6591.26,7108.1 ; C27.1@6591.42,6930.72 6595.5,6926.64 v1(6595.5,6887.85)
  Top Layer w40: J11.5@4686.68,6995.09 4697.82,6983.95 4697.82,6942.28 4710.21,6929.89 4710.21,6799.3 4864.83,6644.69 4864.83,6250.68 5184.32,5931.19 5184.32,5903.89 5155.12,5874.69 v1@5140.68,5874.69 ; J9.5@4923.54,3729.16 4923.54,3768.82 v1@4947.45,3792.73 ; KEY2.2@5079.48,5836.75 5104.22,5836.75 v1(5139.63,5872.16)
  VCC w10: v1@5179.87,5383.54 5179.87,5344.63 5236.97,5287.53 5569.56,5287.53 5577.03,5280.06 5596.08,5280.06 5603.55,5287.53 5642.94,5287.53 v1@5659.88,5304.47 ; v1(5225.5,5102.18) 5329.41,5206.09 5329.41,5285.65 ; v1(5629.88,6115.82) 5629.88,6324.08 v1@5744.92,6439.12 ; v1@5718.48,4764.3 5719.9,4765.73 v1(5766.36,4765.73) ; v1@5751.98,6439.75 6576.48,6439.75 J1.1@6740.25,6603.52 ; v1@6599.65,6888.76 6692.63,6795.78 6692.63,6686.04 6727.65,6651.02 J1.1@6727.65,6606.4
  VCC w40: v1@4136.71,5119.94 4136.71,5019.52 4331.54,4824.69 4331.54,4805.86 ; v1@4944.27,3796.78 4905.36,3796.78 4366.61,4335.53 4366.61,4382.44 4302.68,4446.38 4302.68,4777 4331.54,4805.86 ; v1(5139.63,5872.16) 5386.22,5872.16 v1(5629.88,6115.82) ; 5177.03,4627 4510.4,4627 4331.54,4805.86 ; 5190.13,4622 5249.22,4681.08
  other v1: 4948.42,3790.4 5715.76,4764.09 5861.59,4768.28 4275.41,4864.09 4126.94,5121.77 5176.1,5383.54 5747.24,6439.51
5V: C5.2 C6.1 C17.1 C18.1 C25.1 C26.1 CN1.1 CN2.11 IC1.2 IC1.11 J2.1 J3.2 J6.2 J12.1 L2.2 R24.1 R25.1 R26.2 R27.1 R28.1 R29.2 R30.1 R31.1 R32.2 R33.1 R34.1 R35.2 R36.1 R38.1 R41.2 R44.2 U2.1 U2.3 U3.9 U6.3 U7.3 U8.3 U9.4 U10.4 | length 17097.7
  Top Layer w10: CN2.11@6124.68,3657.3 6129.07,3652.91 v1@6193.7,3652.91
  Top Layer w40: J12.1@3881.43,5691.31 3908.41,5691.31 4050.54,5549.19 4377.92,5549.19 IC1.11@4391.1,5536.01 ; J2.1@4067.75,6708.56 4131.75,6708.56 v1@4138.03,6714.84 ; IC1.2@4981.6,5515.48 5040.58,5515.48 v1@5043.09,5517.99 ; J6.2@5192.38,7017.08 5187.36,7022.1 5187.36,7026.99 5177.47,7036.89 5177.47,7046.89 5184.54,7053.96 5201,7053.96 5216.63,7069.58 5277.52,7069.58 5293.14,7053.96 5382.65,7053.96 5389.72,7046.89 5389.72,6719.35 5448.71,6660.36 R26.2@5456.86,6660.36 ; J3.2@5249.75,3713.07 5249.75,3924.89 5456.86,4132 ; v1(5462,4150.57) 5462,4115.24 R33.1@5468.25,4108.99 ; v1@5465.33,6612.36 R26.2@5465.33,6654.72 ; v1(5513.99,6107.23) 5517.48,6110.71 U6.3@5517.48,6184.13 ; v1(5547.81,6454.99) 5584.83,6454.99 U2.1@5608.46,6431.35 ; R35.2@5548.04,4100.98 5548.04,4152.74 v1@5554.62,4152.74 ; R35.2@5553.6,4097.86 5658.08,4097.86 5659.33,4099.12 R34.1@5665.92,4099.12 ; R25.1@5571.38,6655.34 5575.14,6651.58 5750.21,6651.58 5753.97,6655.34 R28.1@5840.56,6655.34 ; v1(5595.74,6320.85) 5610.35,6335.46 U2.3@5610.35,6347.9 ; R34.1@5675.33,4101 5744.67,4101 5748.43,4104.77 5831.57,4104.77 R31.1@5832.2,4105.39 ; R28.1@5845.27,6655.34 5920.25,6655.34 5957.96,6617.63 v1@5957.96,6616.12 ; R32.2@5932.89,4024.84 5932.89,3983.01 v1@5940,3975.9 ; v1@5973.51,4516.15 5987.95,4530.58 C17.1@6026.85,4530.58 ; C17.1@6030.61,4536.86 6030.61,4494.4 6051.67,4473.35 6094.13,4473.35 C18.1@6106.54,4460.94 ; C25.1@6067.39,6805.94 6070.22,6803.11 C26.1@6161.51,6803.11 ; C6.1@6108.42,4368.7 C18.1@6108.42,4440.23 ; C6.1@6110.3,4361.17 6110.3,4284.62 C5.2@6112.19,4284.62 ; CN1.1@6121.6,7054.68 6319.25,7054.68 U10.4@6348.74,7084.17 ; CN1.1@6134.06,7020.38 6170.46,6983.98 v1@6170.46,6973.94 ; v1@6163.87,6696.29 6163.87,6648.29 R38.1@6166.69,6645.46 ; v1@6167.71,6704.2 C26.1@6167.71,6800.83 ; v1(6234.46,4232.88) 6293.82,4232.88 L2.2@6295.09,4234.16 ; L2.2@6300.74,4238.55 6364.12,4175.17 R36.1@6364.12,4153.21 ; U9.4@6435.91,3638.63 6501.88,3638.63 v1(6507.69,3632.82) ; R44.2@6690.03,3821.86 6698.12,3821.86 6718.53,3842.27 6718.53,3858.19 6746.65,3886.3 6746.65,3903.29 v1@6742.74,3907.19 ; v1@6744,3909.54 6744,3996.76 R41.2@6752.15,4004.92
  VCC w10: U7.3@6952.71,5456.26 U7.3@6964.74,5444.23
  VCC w40: J12.1@3887.77,5695.67 4137.66,5945.56 v1@4137.66,6716.41 ; J12.1@3890.49,5694.57 3922.49,5694.57 4082.5,5534.57 5041.12,5534.57 ; v1@5467.35,6611.66 5467.35,6535.44 v1(5547.81,6454.99) 5547.81,6368.78 v1(5595.74,6320.85) 5595.74,6158.1 5558.75,6121.11 5521.66,6121.11 ; v1@5470.04,6612.52 5487.33,6595.23 5945.94,6595.23 v1@5964.17,6613.46 ; v1(5513.99,6107.23) 5404.17,5997.4 4962.06,5997.4 4954.98,5990.33 4954.98,5980.33 5041.12,5894.2 5041.12,5534.57 ; v1@5552.74,4157.13 5480.49,4157.13 5541.34,4217.99 5541.34,4417.06 5673.92,4417.06 5680.99,4424.14 5890.07,4424.14 v1@5976.65,4510.71 ; v1@5556.51,4159.33 5713.79,4159.33 5894.5,3978.62 5940.52,3978.62 5940.52,3917.44 v1@6193.7,3664.26 ; v1@5966.06,6616.28 6086.53,6616.28 v1@6162.77,6692.52 ; v1@5973.83,4529.7 6373.37,4929.24 6373.37,5471.37 6398.78,5496.79 6464.18,5496.79 U3.9@6462.31,5494.91 ; v1@5976.65,4522.64 v1@5976.65,4510.71 ; v1@6166.69,6690.64 6118.17,6739.16 6118.17,6958.47 6130.82,6971.12 v1@6171.4,6971.12 ; v1@6202.17,3660.49 6202.31,3660.35 6202.31,3571.88 6285.32,3488.87 6399.49,3488.87 6507.83,3597.21 6507.83,3632.68 v1(6507.69,3632.82) 6507.69,3678 v1@6739.6,3909.91 ; v1(6234.46,4232.88) 6151.76,4232.88 6151.15,4232.27 5976.65,4406.78 v1@5976.65,4510.71 ; U3.9@6465.37,5497.97 6465.37,5499.23 6536.35,5570.21 6536.35,5603.78 6572.01,5639.44 6572.01,6042.08 6557.19,6056.9 6312.71,6056.9 5807.32,5551.51 5058.06,5551.51 5041.12,5534.57 ; 6580.13,5648.67 6617.78,5648.67 6620.74,5651.63 6757.35,5651.63 U7.3@6945.78,5463.19 ; v1@6858.65,5451.35 6938.48,5451.35 6945.78,5458.65 U7.3@6945.78,5463.19 ; U7.3@6952.71,5456.26 U7.3@6945.78,5463.19
  Bottom Layer w40: 6831.42,5167.35 U8.3@6948.13,5050.64 ; 6844.38,5172.22 6844.38,5437.17 v1(6858.6,5451.39)
  other v1: 6196.76,3659.26 6740.78,3909.31 5942.01,3974.88 5554.23,4158.1 5971.63,4520.55 5043.09,5518.62 5469.1,6612.36 5961.35,6612.36 6164.81,6695.35 4139.17,6717.23 6169.83,6975.2
14V: C13.2 C14.2 D10.1 D11.1 D12.1 D13.1 J5.1 J10.1 R11.2 SW1.2 U3.4 U5.2 | length 7242.3
  Top Layer w10: SW1.2@5615.25,4319.02 5615.25,4543.44 v1(5617.51,4545.7) ; R11.2@6570.66,3921.48 R11.2@6579.74,3921.48 ; U5.2@6587.13,4013.7 6592.15,4018.72 6580.91,4029.97 6580.91,4085.29 v1@6592.15,4096.53
  Top Layer w40: J5.1@4239.73,6276.55 4285.33,6276.55 v1@4297.46,6264.42 ; v1@4632.22,5917.88 4632.22,5392.69 v1@4643.51,5381.39 ; v1@6059.48,4008.53 6063.87,4004.14 C14.2@6111.56,4004.14 ; U3.4@6279.2,5230.45 6323.67,5274.92 6323.67,5288.51 6365.81,5330.65 6365.81,5768.14 6405.64,5807.96 6405.64,5824.35 6443.92,5862.63 6460.3,5862.63 6517.95,5920.27 J10.1@6517.95,5960.51 ; v1@6326.78,3552.36 6357.53,3521.61 C13.2@6370.7,3521.61 ; D13.1@6389.56,6040.97 6391.22,6040.97 6471.69,5960.51 J10.1@6528.26,5960.51 ; J10.1@6541.2,5954.86 6618.84,5954.86 v1@6621.19,5952.51 ; U5.2@6571.84,4010.83 6587.22,3995.45 R11.2@6587.22,3915.57 ; D12.1@6605.2,5710.64 6622.14,5727.58 v1@6622.14,5765.69 ; 6612.96,5707.11 D11.1@6668.72,5707.11 ; D11.1@6670.84,5703.58 6817.18,5703.58 D10.1@6817.58,5703.18
  VCC w40: v1@4304.67,6275.07 4304.67,6274.51 4630.8,5948.38 v1@4630.8,5919.29 ; v1@4638.02,5380.45 4649.94,5368.53 4897.15,5368.53 5568.21,4697.47 5568.21,4581.01 5585.78,4563.44 5584.83,4562.5 ; 5586.72,4562.5 5599.54,4562.5 ; 5607.27,4554.77 5624.84,4572.34 ; SW1.2@5618.52,4322.73 5641.11,4322.73 5659.07,4304.77 5714.43,4304.77 5868.71,4150.49 5915,4150.49 v1@6055.24,4010.25 ; 5626.7,4572.34 5804.35,4749.99 5804.35,4769.42 6205.64,5170.7 6205.64,5174.35 6243.92,5212.63 6247.56,5212.63 U3.4@6256.16,5221.22 ; v1@6052.42,4006.18 6111.4,3947.19 6135.2,3947.19 6171.91,3983.9 6203.38,3983.9 6225.64,3961.65 6225.64,3949.07 6257.6,3917.1 6409.13,3917.1 6439.22,3947.19 6450.55,3947.19 ; v1@6330.23,3556.12 6328.77,3556.12 6265.03,3619.86 6265.03,3666.24 6370.39,3771.6 6370.39,3866.41 v1@6594.87,4090.88
  Bottom Layer w40: v1@6617.9,5956.27 6617.9,5769.93 v1@6622.14,5765.69
  other v1: 6325.53,3553.61 6053.83,4007.27 6591.13,4092.84 4634.88,5383.59 6620.72,5762.16 4630.8,5912.23 6620.49,5952.27 4298.86,6267.33
$1N6: U1.93
$1N11: U1.37
$1N26: U1.98
$1N33: U1.88
$1N34: U1.87
$1N35: U1.86
$1N60: LED1.2 R2.1 | length 84.4
  Top Layer w10: LED1.2@6076.13,4773.84 6158.12,4773.84 R2.1@6159.79,4775.51
$1N82: LED2.2 R4.2 | length 134.8
  Top Layer w10: R4.2@6252.65,4776.35 6292.81,4776.35 LED2.2@6359.74,4843.28
$1N103: MOS4.1 R22.1 R23.1 | length 197.5
  Top Layer w10: MOS4.1@4245.89,6986.66 4265.65,7006.42 R22.1@4347.54,7006.42 ; R22.1@4349.42,7008.3 4358.83,7017.72 R23.1@4358.83,7092.07
$1N104: GREEN.2 R9.1 RED.2 | length 158.6
  Top Layer w10: RED.2@4408.32,3671.66 RED.2@4409.27,3670.72 ; RED.2@4408.95,3670.41 RED.2@4409.58,3670.41 ; R9.1@4429.66,3595.11 4429.66,3650.33 RED.2@4409.58,3670.41 ; GREEN.2@4482.37,3671.03 4481.74,3670.41 RED.2@4409.58,3670.41
$1N108: C15.2 U5.4 | length 504.1
  Top Layer w10: C15.2@6635.2,3594.4 6686.97,3646.17 6686.97,3756.48 6654.79,3788.66 6654.79,3851.97 6677.46,3874.64 6692.66,3874.64 6699.1,3881.08 6699.1,3944.39 6677.5,3965.99 6677.5,4014.13 U5.4@6686.97,4023.59
$1N109: C16.2 U5.1 | length 178.8
  Top Layer w10: C16.2@6451.9,4165.98 6527.14,4090.73 6527.14,4031.75 U5.1@6536.61,4022.29
$1N110: RED.1 U4.4 | length 146.8
  Top Layer w10: RED.1@4405.81,3731.9 4405.81,3766.41 4452.25,3812.84 4452.25,3856.77 U4.4@4450.36,3858.65
$1N117: GREEN.1 U4.5 | length 122.6
  Top Layer w10: U4.5@4476.09,3853.63 4476.09,3738.17 GREEN.1@4481.11,3733.15
$1N121: C16.1 D3.1 L2.1 U5.8 | length 635.6
  Top Layer w10: D3.1@6250.25,4650.44 6250.25,4345.49 L2.1@6293.54,4302.19 ; L2.1@6293.54,4302.14 6393.44,4302.14 6456.19,4239.39 U5.8@6536.93,4239.39
$1N122: R10.2 U4.7 | length 267.7
  Top Layer w10: U4.7@4526.92,3856.77 4526.92,3592.6 R10.2@4529.43,3590.09
$1N125: MOS3.1 R20.1 R21.1 | length 233.8
  Top Layer w10: MOS3.1@5193.4,4215.4 R21.1@5193.4,4339.05 ; R21.1@5194.02,4344.05 5202.14,4352.16 R20.1@5202.14,4450.84
$1N133: C23.1 C24.1 U5.6 | length 237.6
  Top Layer w10: C23.1@6494.78,4350.98 C24.1@6578.44,4350.98 ; C24.1@6583.04,4354.32 6626.77,4310.59 6626.77,4222.56 U5.6@6623.91,4219.7
$1N139: L1.2 R15.2 R16.2 U4.11 | length 437.4
  Top Layer w10: R16.2@4240.43,4064.12 4253.58,4077.27 4253.58,4091.41 4258.5,4096.33 4258.5,4194.2 4264.49,4200.19 4387.7,4200.19 4388.89,4198.99 4395.01,4198.99 4396.52,4197.48 4414.89,4197.48 4441.3,4171.07 R15.2@4441.3,4164.44 ; R15.2@4441.3,4163.6 R15.2@4441.3,4164.44 ; U4.11@4449.67,4072.41 4444.47,4077.6 4444.47,4112.58 4443.69,4113.36 4443.69,4157.37 4442.97,4158.09 R15.2@4441.3,4164.44
$1N155: R13.2 U4.8 | length 249.5
  Top Layer w10: U4.8@4528.03,4074.08 4613.51,4074.08 4698.9,4159.47 R13.2@4742.18,4159.47
$1N156: R14.2 R40.1 U4.9 | length 199.1
  Top Layer w10: U4.9@4500.42,4072.69 4509.12,4081.38 4509.12,4139.11 R40.1@4530.4,4160.39 ; R40.1@4529.98,4160.81 R40.1@4530.82,4160.81 ; R40.1@4531.94,4161.93 R40.1@4530.82,4160.81 ; R14.2@4618.11,4171.41 4618.11,4163.12 4615.8,4160.81 R40.1@4530.82,4160.81
$1N159: C10.1 U4.14 | length 98.6
  Top Layer w10: C10.1@4360.44,4165.51 4374.24,4151.7 U4.14@4374.24,4072.64
$1N166: C11.2 R13.1 | length 144.5
  Top Layer w10: 4704.29,4242.06 4706.66,4244.42 4833.82,4244.42 C11.2@4843.72,4234.53
$1N211: R11.1 WHITE.2 | length 457.8
  Top Layer w10: WHITE.2@6558.02,3579.34 6551.89,3585.47 6551.89,3628.74 6558.97,3635.81 6651.2,3635.81 6664.38,3648.99 6664.38,3759.25 6640.78,3782.86 6640.78,3857.78 6664.38,3881.38 R11.1@6664.38,3914.41
$1N220: C23.2 R12.2 | length 92.4
  Top Layer w10: R12.2@6404.22,4428.78 6493.94,4428.78 C23.2@6495.83,4430.66
$1N221: R42.1 R43.2 | length 94.5
  Top Layer w10: R43.2@6675.07,4340.94 6734.06,4340.94 R42.1@6759.15,4315.84
$1N223: LED5white.2 R44.1 | length 307.6
  Top Layer w10: R44.1@6766.97,3822.17 6766.97,3517.22 LED5white.2@6768.85,3515.34
$1N8956: MOS1.1 U4.1 | length 81.5
  Top Layer w10: MOS1.1@4298.42,3867.88 4358.66,3867.88 U4.1@4373.72,3852.82
$1N9104: D1.2 MOS1.3 | length 774.6
  Top Layer w10: MOS1.3@4122.03,3870.22 4169.09,3870.22 v1@4179.44,3880.57 ; v1@4330.97,4367.18 4382.74,4367.18 4415.74,4400.17 4415.74,4454.71 D1.2@4405.31,4465.14
  Bottom Layer w10: v1@4177.56,3882.46 4291.44,3996.34 4291.44,4328.59 v1@4328.15,4365.29
  other v1: 4177.09,3879.16 4328.62,4366.71
$1N9650: MOS2.1 R18.1 R19.1 | length 223
  Top Layer w10: MOS2.1@5144.95,6543.03 5154.99,6532.99 R19.1@5154.99,6419.42 ; R19.1@5151.85,6419.42 5157.5,6413.77 R18.1@5157.5,6326.55
$1N9865: D1.1 D2.1 L1.1 | length 380.9
  Top Layer w10: 4215.2,4370.46 4237.92,4393.17 4237.92,4479.51 4227.01,4490.42 D2.1@4227.01,4614.24 ; 4216.46,4370.46 4216.46,4293.95 4247.8,4262.6 L1.1@4250.13,4262.6
$1N10537: LED4white.2 R17.1 | length 88.8
  Top Layer w10: R17.1@6671.52,7113.26 6704.15,7080.64 LED4white.2@6746.81,7080.64
$1N18842: R36.2 U9.1 | length 150
  Top Layer w10: R36.2@6283.74,4155.31 6320.13,4118.92 U9.1@6320.13,4020.4
$1N19000: R38.2 U10.1 | length 242.6
  Top Layer w10: R38.2@6235.11,6640.62 6372.53,6640.62 U10.1@6446.88,6714.98
$1N27321: U1.36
